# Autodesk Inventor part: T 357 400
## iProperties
Created: 2005-12
Part Number: T 357 400
Material: 2.0401.26
Document SubType Name: Modeling
Designer: I.Baliuc
Manufacturer: Standard
Standards Organization: Custom
Description: Welle
Density: 8.2 g/cm^3
Title: Welle
Company: Mayer & Müller AG Schaltgeräte
HalbzeugNorm: DIN 1761
Zweck: als Federsockel
Abmessung: Vkt 20
Author: T.Messerschmitt
Revision Number: 357400
Keywords: 382076
Comments: Ersatz für Zeichnung von 14.04.05
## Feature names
1. Extrusion2
2. Bohrung1 [Hole]
3. Extrusion3
4. Bohrung_M8x15 [Hole]
5. Spiegeln1 [Mirror]
